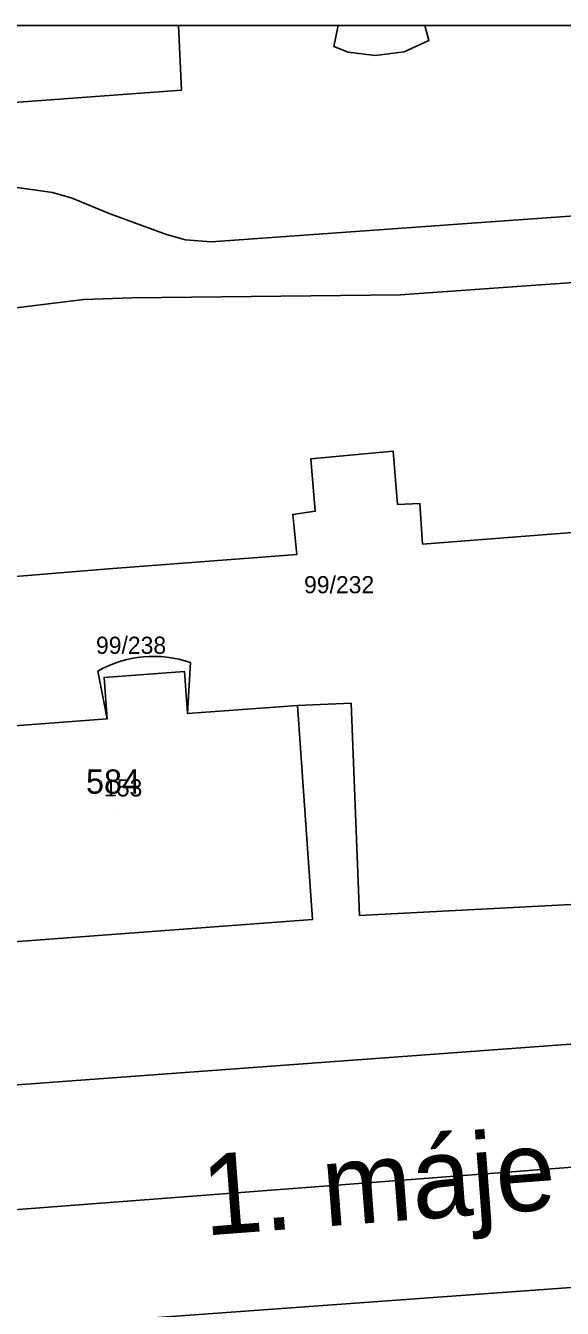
# Model space of a CAD drawing. Extents: x -873642 to -872917, y -1012962 to -1012567.
# Drawn here: x -873435 to -873408.4, y -1012631 to -1012567.5 of the extents above; entities that cross this region are included whole.
import ezdxf

# ---------------------------------------------------------------- set-up
doc = ezdxf.new("R2010")
doc.units = 0
for name, color, linetype in [('adresni_misto', 7, 'Continuous'), ('cisla_parcelni_kn', 7, 'Continuous'), ('cislo_domovni', 7, 'Continuous'), ('osy_ulic', 7, 'Continuous'), ('parcely_kn', 7, 'Continuous'), ('stavebni_objekty_bydleni', 7, 'Continuous'), ('TRASY - zamereno', 7, 'Continuous'), ('ulice', 7, 'Continuous')]:
    doc.layers.add(name, color=color, linetype=linetype)

msp = doc.modelspace()

# ---------------------------------------------------------------- linework, layer by layer
at = {"layer": 'adresni_misto'}
msp.add_line((-873430.43, -1012606.44), (-873430.43, -1012606.44), dxfattribs=at)
at = {"layer": 'osy_ulic'}
msp.add_lwpolyline([(-872916.927, -1012586.659), (-872957.62, -1012590.24), (-872977.73, -1012591.46), (-872994.83, -1012592.51), (-873031.96, -1012595.34), (-873059.56, -1012597.3), (-873096.52, -1012600.28), (-873281.07, -1012614.36), (-873481.95, -1012629.68)], dxfattribs=at)
at = {"layer": 'parcely_kn'}
for p, q in [((-873427.436, -1012567.5), (-873445.635, -1012567.5)), ((-873427.436, -1012567.5), (-873445.635, -1012567.5)), ((-873419.525, -1012567.5), (-873427.436, -1012567.5)), ((-873419.525, -1012567.5), (-873427.436, -1012567.5)), ((-873415.236, -1012567.5), (-873419.525, -1012567.5)), ((-873415.236, -1012567.5), (-873419.525, -1012567.5)), ((-873340.542, -1012567.5), (-873415.236, -1012567.5)), ((-873340.542, -1012567.5), (-873415.236, -1012567.5))]:
    msp.add_line(p, q, dxfattribs=at)
for points in [[(-873427.436, -1012567.5), (-873427.29, -1012570.69), (-873445.24, -1012572.02), (-873445.21, -1012572.41), (-873446.29, -1012572.49), (-873453.3, -1012572.07), (-873454.3, -1012572.03), (-873456.29, -1012572.12), (-873457.3, -1012572.25), (-873458.26, -1012572.43), (-873461.15, -1012573.28), (-873462.12, -1012573.52), (-873462.71, -1012573.49), (-873462.01, -1012572.83), (-873455.607, -1012567.5)], [(-873427.436, -1012567.5), (-873427.29, -1012570.69), (-873445.24, -1012572.02), (-873445.21, -1012572.41), (-873446.29, -1012572.49), (-873453.3, -1012572.07), (-873454.3, -1012572.03), (-873456.29, -1012572.12), (-873457.3, -1012572.25), (-873458.26, -1012572.43), (-873461.15, -1012573.28), (-873462.12, -1012573.52), (-873462.71, -1012573.49), (-873462.01, -1012572.83), (-873455.607, -1012567.5)], [(-873445.635, -1012567.5), (-873445.24, -1012572.02), (-873427.29, -1012570.69), (-873427.436, -1012567.5)], [(-873445.635, -1012567.5), (-873445.24, -1012572.02), (-873427.29, -1012570.69), (-873427.436, -1012567.5)], [(-873419.525, -1012567.5), (-873419.74, -1012568.53), (-873419.03, -1012568.81), (-873417.69, -1012568.97), (-873416.26, -1012568.79), (-873415.03, -1012568.23), (-873415.236, -1012567.5)], [(-873415.236, -1012567.5), (-873415.03, -1012568.23), (-873416.26, -1012568.79), (-873417.69, -1012568.97), (-873419.03, -1012568.81), (-873419.74, -1012568.53), (-873419.525, -1012567.5)], [(-873419.525, -1012567.5), (-873419.74, -1012568.53), (-873419.03, -1012568.81), (-873417.69, -1012568.97), (-873416.26, -1012568.79), (-873415.03, -1012568.23), (-873415.236, -1012567.5)], [(-873415.236, -1012567.5), (-873415.03, -1012568.23), (-873416.26, -1012568.79), (-873417.69, -1012568.97), (-873419.03, -1012568.81), (-873419.74, -1012568.53), (-873419.525, -1012567.5)], [(-873435.68, -1012575.49), (-873433.69, -1012575.76), (-873432.72, -1012576.04), (-873430.88, -1012576.81), (-873428.04, -1012577.84), (-873427.1, -1012578.1), (-873425.82, -1012578.21), (-873394.9, -1012575.99)], [(-873435.68, -1012575.49), (-873433.69, -1012575.76), (-873432.72, -1012576.04), (-873430.88, -1012576.81), (-873428.04, -1012577.84), (-873427.1, -1012578.1), (-873425.82, -1012578.21), (-873394.9, -1012575.99)], [(-873435.68, -1012575.49), (-873433.69, -1012575.76), (-873432.72, -1012576.04), (-873430.88, -1012576.81), (-873428.04, -1012577.84), (-873427.1, -1012578.1), (-873425.82, -1012578.21), (-873394.9, -1012575.99)], [(-873435.68, -1012575.49), (-873433.69, -1012575.76), (-873432.72, -1012576.04), (-873430.88, -1012576.81), (-873428.04, -1012577.84), (-873427.1, -1012578.1), (-873425.82, -1012578.21), (-873394.9, -1012575.99)], [(-873400.89, -1012592.06), (-873415.35, -1012593.18), (-873415.48, -1012591.17), (-873416.59, -1012591.21), (-873416.8, -1012588.58), (-873420.89, -1012588.96), (-873420.67, -1012591.55), (-873421.78, -1012591.71), (-873421.58, -1012593.69), (-873430.92, -1012594.41), (-873457.37, -1012596.59)], [(-873457.37, -1012596.59), (-873430.92, -1012594.41), (-873421.58, -1012593.69), (-873421.78, -1012591.71), (-873420.67, -1012591.55), (-873420.89, -1012588.96), (-873416.8, -1012588.58), (-873416.59, -1012591.21), (-873415.48, -1012591.17), (-873415.35, -1012593.18), (-873400.89, -1012592.06)], [(-873400.89, -1012592.06), (-873415.35, -1012593.18), (-873415.48, -1012591.17), (-873416.59, -1012591.21), (-873416.8, -1012588.58), (-873420.89, -1012588.96), (-873420.67, -1012591.55), (-873421.78, -1012591.71), (-873421.58, -1012593.69), (-873430.92, -1012594.41), (-873457.37, -1012596.59)], [(-873457.37, -1012596.59), (-873430.92, -1012594.41), (-873421.58, -1012593.69), (-873421.78, -1012591.71), (-873420.67, -1012591.55), (-873420.89, -1012588.96), (-873416.8, -1012588.58), (-873416.59, -1012591.21), (-873415.48, -1012591.17), (-873415.35, -1012593.18), (-873400.89, -1012592.06)], [(-873143.44, -1012597.91), (-873216.55, -1012603.73), (-873279.94, -1012608.27), (-873348.3, -1012613.15), (-873406.66, -1012617.85), (-873469.84, -1012622.48), (-873491.33, -1012623.66), (-873566.46, -1012629.92), (-873583.11, -1012630.93), (-873584.28, -1012631.65), (-873606.27, -1012634.41), (-873608.98, -1012633.05), (-873615.37, -1012633.09), (-873642.294, -1012633.957)], [(-873403, -1012597.67), (-873402.46, -1012600.06), (-873407.85, -1012600.46), (-873407.04, -1012610.98), (-873418.47, -1012611.57), (-873418.89, -1012601.06), (-873421.55, -1012601.17), (-873427, -1012601.56), (-873426.85, -1012599.05)], [(-873403, -1012597.67), (-873402.46, -1012600.06), (-873407.85, -1012600.46), (-873407.04, -1012610.98), (-873418.47, -1012611.57), (-873418.89, -1012601.06), (-873421.55, -1012601.17), (-873427, -1012601.56), (-873426.85, -1012599.05)], [(-873426.85, -1012599.05), (-873427, -1012601.56), (-873427.15, -1012599.48), (-873431.13, -1012599.78)], [(-873426.85, -1012599.05), (-873427, -1012601.56), (-873427.15, -1012599.48), (-873431.13, -1012599.78)], [(-873431.45, -1012599.47), (-873430.98, -1012601.84), (-873439.07, -1012602.45), (-873447.57, -1012603.1), (-873447.38, -1012600.59)], [(-873431.45, -1012599.47), (-873430.98, -1012601.84), (-873439.07, -1012602.45), (-873447.57, -1012603.1), (-873447.38, -1012600.59)], [(-873431.13, -1012599.78), (-873430.98, -1012601.84), (-873431.45, -1012599.47)], [(-873431.13, -1012599.78), (-873430.98, -1012601.84), (-873431.45, -1012599.47)], [(-873407.04, -1012610.98), (-873418.47, -1012611.57), (-873418.89, -1012601.06), (-873421.55, -1012601.17), (-873420.8, -1012611.77), (-873438.29, -1012613.07), (-873455.75, -1012614.36), (-873473.21, -1012615.66), (-873473.99, -1012605.07), (-873468.6, -1012604.57), (-873469.25, -1012602.07), (-873475.15, -1012602.79), (-873475.18, -1012602.94), (-873475.17, -1012603.26), (-873477.49, -1012605.2), (-873479.94, -1012609.19), (-873478.69, -1012616.29), (-873476.71, -1012619.07), (-873473.56, -1012621.85), (-873469.84, -1012622.48), (-873406.66, -1012617.85)], [(-873407.04, -1012610.98), (-873418.47, -1012611.57), (-873418.89, -1012601.06), (-873421.55, -1012601.17), (-873420.8, -1012611.77), (-873438.29, -1012613.07), (-873455.75, -1012614.36), (-873473.21, -1012615.66), (-873473.99, -1012605.07), (-873468.6, -1012604.57), (-873469.25, -1012602.07), (-873475.15, -1012602.79), (-873475.18, -1012602.94), (-873475.17, -1012603.26), (-873477.49, -1012605.2), (-873479.94, -1012609.19), (-873478.69, -1012616.29), (-873476.71, -1012619.07), (-873473.56, -1012621.85), (-873469.84, -1012622.48), (-873406.66, -1012617.85)], [(-873642.294, -1012646.913), (-873615.37, -1012644.94), (-873586.69, -1012643.34), (-873548.73, -1012640.58), (-873509.03, -1012637.61), (-873492.26, -1012636.3), (-873470.15, -1012634.51), (-873407.08, -1012629.93), (-873286.69, -1012620.81), (-873282.45, -1012620.53), (-873276.73, -1012620.14), (-873273.72, -1012619.94), (-873079.43, -1012607.12)], [(-873095.85, -1012678.72), (-873263.61, -1012691.39), (-873266.56, -1012691.78), (-873320.85, -1012695.55), (-873397.76, -1012701.2), (-873419.57, -1012702.63), (-873457.18, -1012705.12), (-873461.77, -1012705), (-873467.35, -1012700.29), (-873470.31, -1012685.53), (-873471.34, -1012679.34), (-873473.95, -1012664.84), (-873474.55, -1012659.21), (-873476.91, -1012642.49), (-873476.25, -1012638.16), (-873474.09, -1012635.88), (-873470.15, -1012634.51), (-873407.08, -1012629.93)], [(-873095.85, -1012678.72), (-873263.61, -1012691.39), (-873266.56, -1012691.78), (-873320.85, -1012695.55), (-873397.76, -1012701.2), (-873419.57, -1012702.63), (-873457.18, -1012705.12), (-873461.77, -1012705), (-873467.35, -1012700.29), (-873470.31, -1012685.53), (-873471.34, -1012679.34), (-873473.95, -1012664.84), (-873474.55, -1012659.21), (-873476.91, -1012642.49), (-873476.25, -1012638.16), (-873474.09, -1012635.88), (-873470.15, -1012634.51), (-873407.08, -1012629.93)]]:
    msp.add_lwpolyline(points, dxfattribs=at)
msp.add_lwpolyline([(-873439.07, -1012602.45), (-873430.98, -1012601.84), (-873431.13, -1012599.78), (-873427.15, -1012599.48), (-873427, -1012601.56), (-873421.55, -1012601.17), (-873420.8, -1012611.77), (-873438.29, -1012613.07)], close=True, dxfattribs=at)
msp.add_lwpolyline([(-873439.07, -1012602.45), (-873430.98, -1012601.84), (-873431.13, -1012599.78), (-873427.15, -1012599.48), (-873427, -1012601.56), (-873421.55, -1012601.17), (-873420.8, -1012611.77), (-873438.29, -1012613.07)], close=True, dxfattribs=at)
for start, end in [(70.74932, 119.68446), (70.74923, 119.68455), (70.74932, 119.68446), (70.74923, 119.68455)]:
    msp.add_arc((-873428.689, -1012604.314), 5.576, start, end, dxfattribs=at)
at = {"layer": 'stavebni_objekty_bydleni'}
msp.add_line((-873427.436, -1012567.5), (-873445.635, -1012567.5), dxfattribs=at)
msp.add_lwpolyline([(-873445.635, -1012567.5), (-873445.24, -1012572.02), (-873427.29, -1012570.69), (-873427.436, -1012567.5)], dxfattribs=at)
msp.add_lwpolyline([(-873438.29, -1012613.07), (-873439.07, -1012602.45), (-873430.98, -1012601.84), (-873431.13, -1012599.78), (-873427.15, -1012599.48), (-873427, -1012601.56), (-873421.55, -1012601.17), (-873420.8, -1012611.77)], close=True, dxfattribs=at)
at = {"layer": 'TRASY - zamereno'}
for p, q in [((-873416.45, -1012580.83), (-873407.4, -1012580.18)), ((-873429.75, -1012580.98), (-873416.45, -1012580.83)), ((-873438.86, -1012581.88), (-873432.13, -1012581.07)), ((-873432.13, -1012581.07), (-873429.75, -1012580.98))]:
    msp.add_line(p, q, dxfattribs=at)

# ---------------------------------------------------------------- texts
at = {"layer": 'cisla_parcelni_kn'}
for s, p in [('99/232', (-873421.221, -1012595.613)), ('99/232', (-873421.221, -1012595.613)), ('99/238', (-873431.533, -1012598.613)), ('99/238', (-873431.533, -1012598.613)), ('153', (-873431.133, -1012605.675)), ('153', (-873431.133, -1012605.675))]:
    msp.add_text(s, height=0.85, dxfattribs=at).set_placement(p)
at = {"layer": 'cislo_domovni'}
msp.add_text('584', height=1.2, dxfattribs=at).set_placement((-873432.03, -1012605.54))
at = {"layer": 'ulice'}
msp.add_text('1. máje', height=4, rotation=4.36119, dxfattribs=at).set_placement((-873426.13, -1012627.429))

doc.saveas('drawing.dxf')
